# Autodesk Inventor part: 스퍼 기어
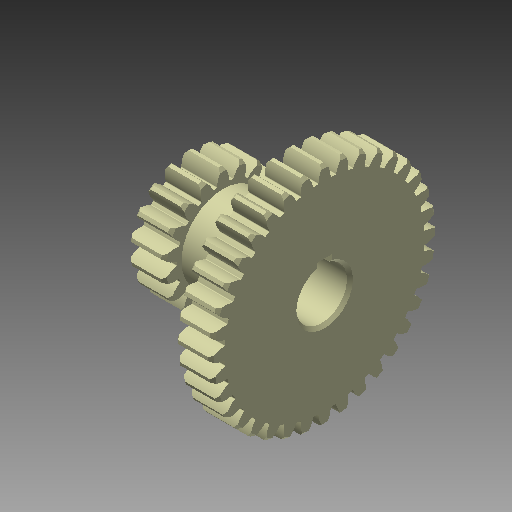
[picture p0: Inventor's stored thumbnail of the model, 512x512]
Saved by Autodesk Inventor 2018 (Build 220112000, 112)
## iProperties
Created: 2024-01
Part Number: 스퍼 기어
Material: 강철, 탄소
Document SubType Name: Modeling
Designer: mdu-01
Density: 1 g/cm^3
Appearance: 기본값(1)
Author: mdu-01
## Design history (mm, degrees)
sketch "스케치1"
  geometry: L1 (0, 0)-(46, 0); L2 (46, 9.5)-(46, 33.5); L3 (46, 33.5)-(34, 33.5); L4 (34, 33.5)-(34, 14); L5 (34, 14)-(12, 14); L6 (12, 14)-(12, 15.5); L7 (12, 15.5)-(0, 15.5); L8 (0, 15.5)-(0, 9.5); L9 (1, 8.5)-(45, 8.5); L10 (0, 9.5)-(1, 8.5); L11 (46, 9.5)-(45, 8.5); 4 further points
  constraints: 22 end point, 7 parallel, 7 point on line, 2 perpendicular, 1 horizontal
  dimensions: "d0" = 46 distance between parallel lines of L2 L8; "d2" = 36 diameter of point (0, 18) L1; "d3" = 2.5 distance from line of L7 point (0, 18); "d4" = 12 distance between parallel lines of L6 L8; "d5" = 28 diameter of L5 L1; "d6" = 17 diameter of L9 L1; "d7" = 72 diameter of point (46, 36) L1; "d9" = 2.5 distance from line of L3 point (46, 36); "d10" = 1 distance of L8.end point (0, 8.5); "d11" = 1 distance of L9.start point (0, 8.5) (= d10); "d12" = 1 distance of L2.start point (46, 8.5) (= d10); "d13" = 1 distance of L9.end point (46, 8.5) (= d12)
revolve "회전1" sketch "스케치1" stored, may be unused: angle "d14" = 90 deg
sketch "스케치2" dims "d15" = 2.5
  geometry: L1 (0, 0)-(0, 20); A1 r 20 centre (0, 0) between (0.57, 19.992) and (-0.57, 19.992); A2 r 9.478 centre (-7.394, 14.854) between (2.07, 15.361) and (0.57, 19.992); A3 r 9.478 centre (7.394, 14.854) between (-0.57, 19.992) and (-2.07, 15.361); A4 r 15.5 centre (0, 0) between (2.07, 15.361) and (-2.07, 15.361); 2 further points
  constraints: 10 point on circle, 4 centre point, 3 symmetric about line, 2 end point, 1 coincident, 1 vertical, 6 other
  dimensions: "d16" = 2 dimension on A1; "d17" = 1.57 distance from line of point (1.57, 17.931) L1; "d18" = 1 horizontal distance of A1.start point (1.57, 17.931); "d19" = 0.5 horizontal distance of A2.start point (1.57, 17.931)
extrude "돌출1" join sketch "스케치2" stored distance "d20" = 10; taper "d21" = 0 deg
chamfer "모따기1" distance "d22" = 1; stored, may be unused: second distance "d23" = 2, angle "d24" = 45 deg
fillet "모깎기1" dims "d25" = 0.25
sketch "스케치3" dims "d29" = 2.5
  geometry: L1 (0, 0)-(0, 38); A1 r 38 centre (0, 0) between (0.57, 37.996) and (-0.57, 37.996); A2 r 9.246 centre (-7.162, 32.926) between (2.07, 33.436) and (0.57, 37.996); A3 r 9.246 centre (7.162, 32.926) between (-0.57, 37.996) and (-2.07, 33.436); A4 r 33.5 centre (0, 0) between (2.07, 33.436) and (-2.07, 33.436); 2 further points
  constraints: 10 point on circle, 4 centre point, 3 symmetric about line, 2 coincident, 2 end point, 1 vertical, 6 other
  dimensions: "d30" = 2 dimension on A1; "d31" = 1.57 distance from line of point (1.57, 35.966) L1; "d32" = 0.5 horizontal distance of A2.start point (1.57, 35.966); "d33" = 1 horizontal distance of A1.start point (1.57, 35.966)
extrude "돌출2" join sketch "스케치3" stored distance "d34" = 0; taper "d35" = 0 deg
chamfer "모따기2" distance "d36" = 1; stored, may be unused: second distance "d37" = 2, angle "d38" = 45 deg
fillet "모깎기2" dims "d39" = 0.25
sketch "스케치4"
  geometry: L1 (-2.5, 8.124)-(2.5, 8.124); L2 (2.5, 8.124)-(2.5, 10.8); L3 (2.5, 10.8)-(-2.5, 10.8); L4 (-2.5, 10.8)-(-2.5, 8.124); A1 r 8.5 centre (0, 0) between (-2.5, 8.124) and (2.5, 8.124) reference; 2 further points
  constraints: 8 end point, 3 point on circle, 2 parallel, 1 horizontal, 1 perpendicular, 1 vertical alignment
  dimensions: "d43" = 5 distance between parallel lines of L2 L4; "d45" = 19.3 distance from line of point (0, -8.5) L3
extrude "돌출3" cut sketch "스케치4" extent not by distance; stored distance "d46" = 10; taper "d47" = 0 deg
node "솔리드1"
pattern_circular "원형 패턴1" dims angle "d27" = 360 deg
pattern_circular "원형 패턴2" dims angle "d41" = 360 deg
